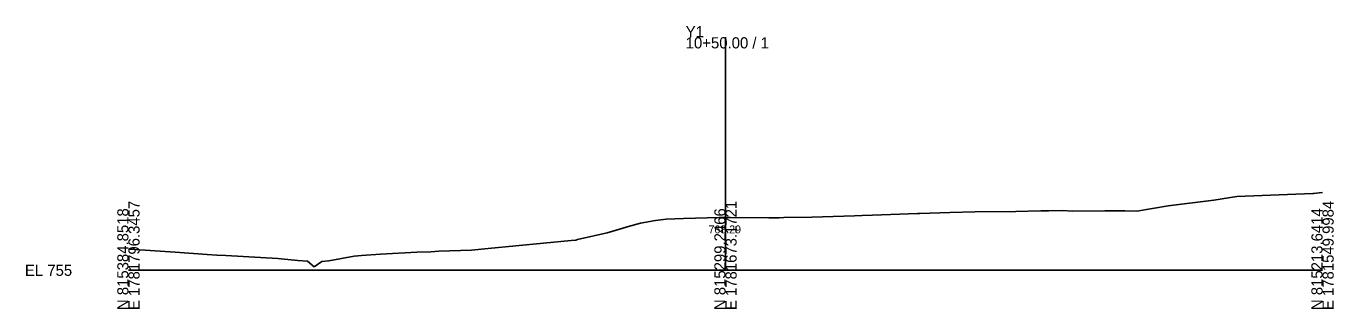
# Model space of a CAD drawing. Extents: x -26 to 3603, y -10 to 9847.
# Drawn here: x -25.7 to 302.8, y 490.3 to 561.4 of the extents above; entities that cross this region are included whole.
import ezdxf

# ---------------------------------------------------------------- set-up
doc = ezdxf.new("R2010")
doc.units = 0
for name, color, linetype in [('Exist Cross Section Cell', 7, 'Continuous'), ('Exist XS Center Line Elevation Label', 7, 'Continuous'), ('Exist XS Ground Line', 7, 'Continuous')]:
    doc.layers.add(name, color=color, linetype=linetype)

msp = doc.modelspace()

# ---------------------------------------------------------------- linework, layer by layer
at = {"layer": 'Exist Cross Section Cell'}
for p, q in [((150, 500), (150, 558.61)), ((0, 500), (150, 500)), ((150, 500), (300, 500))]:
    msp.add_line(p, q, dxfattribs=at)
at = {"layer": 'Exist XS Ground Line'}
for p, q in [((278.45, 518.57), (297.53, 519.33)), ((297.53, 519.33), (297.85, 519.35)), ((297.85, 519.35), (299.13, 519.46)), ((299.13, 519.46), (300, 519.54)), ((253.32, 514.9), (261.23, 516.22)), ((261.23, 516.22), (272.67, 517.66)), ((272.67, 517.66), (278.45, 518.57)), ((128.62, 511.83), (132.4, 512.54)), ((132.4, 512.54), (135.13, 512.85)), ((135.13, 512.85), (139.46, 513.06)), ((139.46, 513.06), (148.43, 513.25)), ((148.43, 513.25), (149.91, 513.29)), ((149.91, 513.29), (151.25, 513.28)), ((151.25, 513.28), (160.9, 513.21)), ((160.9, 513.21), (161.78, 513.2)), ((161.78, 513.2), (162.34, 513.21)), ((162.34, 513.21), (163.49, 513.24)), ((163.49, 513.24), (164.69, 513.27)), ((164.69, 513.27), (171.68, 513.39)), ((171.68, 513.39), (174.4, 513.44)), ((174.4, 513.44), (182.38, 513.71)), ((182.38, 513.71), (184.3, 513.76)), ((184.3, 513.76), (186.97, 513.85)), ((186.97, 513.85), (198.24, 514.26)), ((198.24, 514.26), (198.84, 514.28)), ((198.84, 514.28), (201.3, 514.38)), ((201.3, 514.38), (206.38, 514.51)), ((206.38, 514.51), (212.61, 514.67)), ((212.61, 514.67), (222.91, 514.83)), ((222.91, 514.83), (229.25, 514.95)), ((229.25, 514.95), (231.27, 514.98)), ((231.27, 514.98), (234.57, 515.03)), ((234.57, 515.03), (237.18, 514.91)), ((237.18, 514.91), (245.28, 514.95)), ((245.28, 514.95), (250.32, 514.92)), ((250.32, 514.92), (253.32, 514.9)), ((112.85, 507.72), (120.24, 509.47)), ((120.24, 509.47), (123.93, 510.51)), ((123.93, 510.51), (125.34, 510.97)), ((125.34, 510.97), (128.62, 511.83)), ((90.39, 505.48), (111.22, 507.51)), ((111.22, 507.51), (112.41, 507.62)), ((112.41, 507.62), (112.85, 507.72)), ((0, 505.36), (4.19, 505.07)), ((4.19, 505.07), (11.73, 504.59)), ((11.73, 504.59), (19.77, 503.97)), ((19.77, 503.97), (22.19, 503.84)), ((22.19, 503.84), (24.49, 503.72)), ((24.49, 503.72), (37.5, 502.99)), ((37.5, 502.99), (42.59, 502.51)), ((50.32, 502.41), (56.7, 503.52)), ((56.7, 503.52), (58.52, 503.69)), ((58.52, 503.69), (63.35, 504.1)), ((63.35, 504.1), (72.45, 504.54)), ((72.45, 504.54), (75.94, 504.68)), ((75.94, 504.68), (78.01, 504.78)), ((78.01, 504.78), (86.22, 505.1)), ((86.22, 505.1), (90.39, 505.48)), ((42.59, 502.51), (45, 502.32)), ((45, 502.32), (46.64, 500.88)), ((46.64, 500.88), (48.56, 502.22)), ((48.56, 502.22), (50.32, 502.41))]:
    msp.add_line(p, q, dxfattribs=at)

# ---------------------------------------------------------------- texts
at = {"layer": 'Exist Cross Section Cell'}
for s, p in [('Y1', (140, 558.61)), ('10+50.00 / 1', (140, 555.81)), ('EL 755', (-26, 498.6))]:
    msp.add_text(s, height=2.8, dxfattribs=at).set_placement(p)
for s, p in [('E 1781796.3457', (2.8, 490)), ('E 1781673.1721', (152.8, 490)), ('E 1781549.9984', (302.8, 490)), ('N 815384.8518', (0, 490)), ('N 815299.2466', (150, 490)), ('N 815213.6414', (300, 490))]:
    msp.add_text(s, height=2.8, rotation=90, dxfattribs=at).set_placement(p)
at = {"layer": 'Exist XS Center Line Elevation Label'}
msp.add_text('768.29', height=2, dxfattribs=at).set_placement((145.73, 509.29))

doc.saveas('drawing.dxf')
